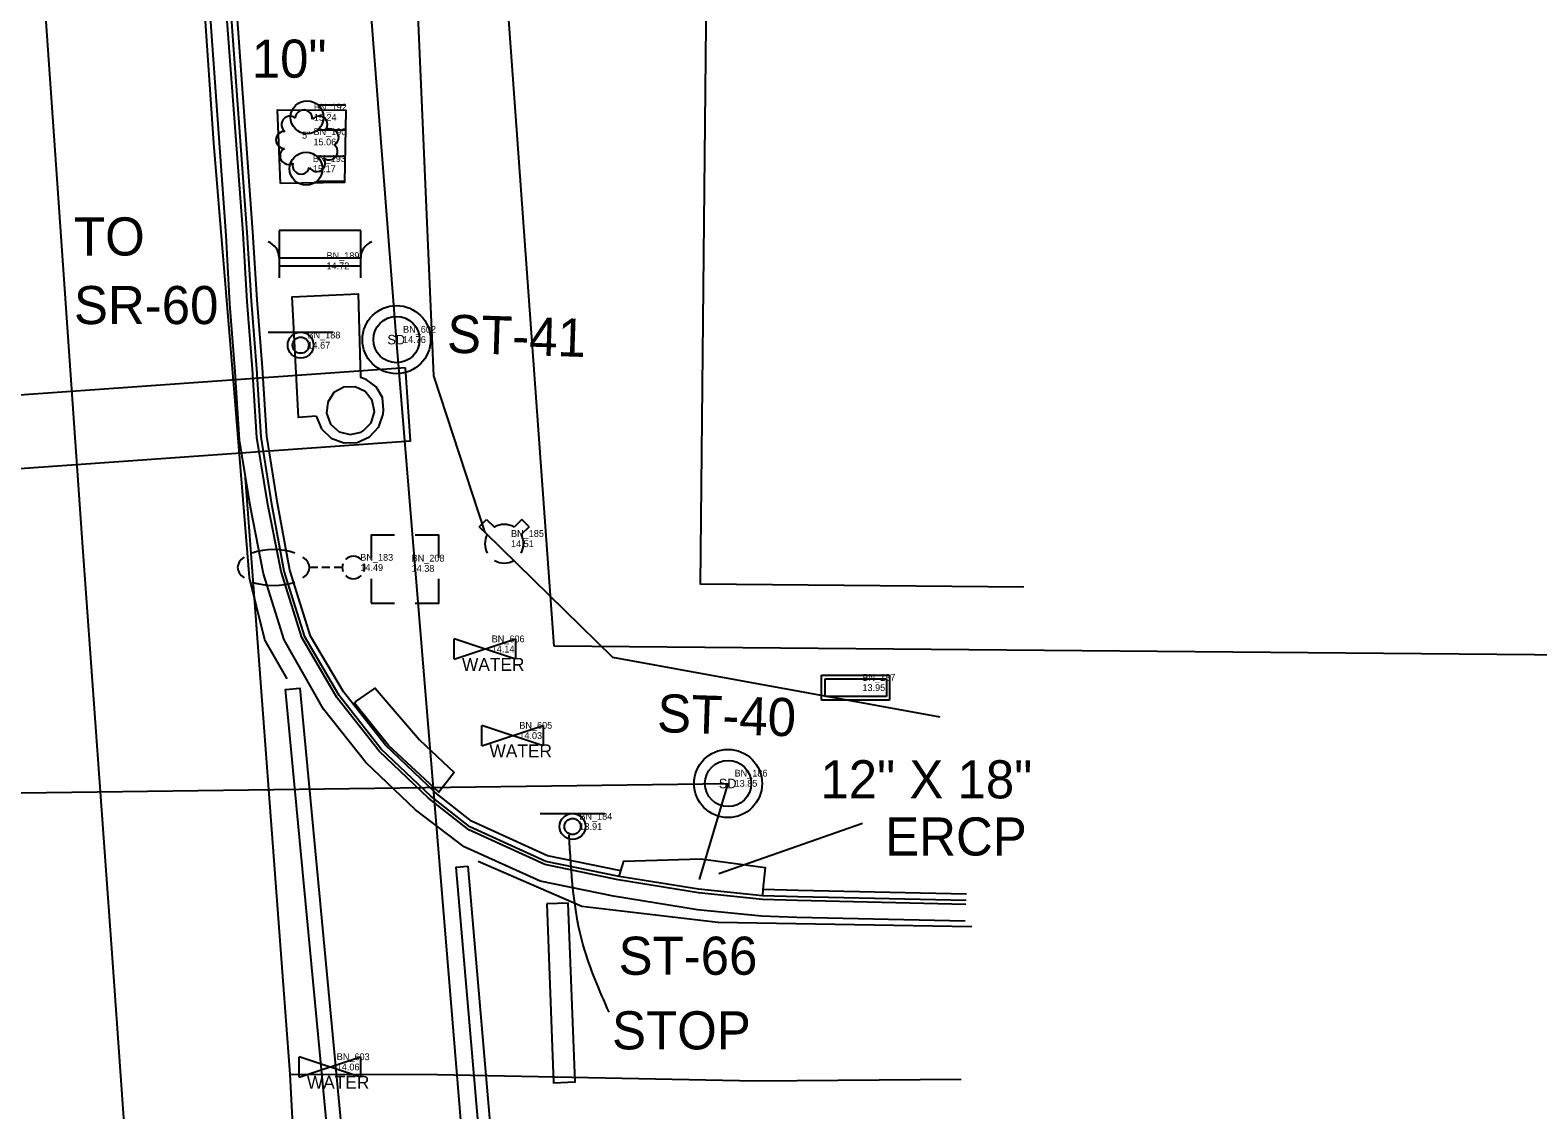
# Model space of a CAD drawing. Extents: x 509744 to 512285, y 1314862 to 1316822.
# Drawn here: x 511240.3 to 511351, y 1315303.3 to 1315382.6 of the extents above; entities that cross this region are included whole.
import ezdxf

# ---------------------------------------------------------------- set-up
doc = ezdxf.new("R2010")
doc.units = 0
for name, color, linetype in [('Bench_ep', 7, 'Continuous'), ('Building_ep', 7, 'Continuous'), ('CGBack_ep', 7, 'Continuous'), ('CGep_ep', 7, 'Continuous'), ('CGFace_ep', 7, 'Continuous'), ('CurbRampWarning_ep', 7, 'Continuous'), ('FireHydrant_ep', 7, 'Continuous'), ('FloodLight_ep', 7, 'Continuous'), ('InletCurb_ep', 7, 'Continuous'), ('JunctBox_ep', 7, 'Continuous'), ('LaneLine_ep', 7, 'Continuous'), ('Luminaire_ep', 7, 'Continuous'), ('ManholeSW_ep', 7, 'Continuous'), ('NonPlottingEle_dp', 7, 'Continuous'), ('PavtAsphalt_ep', 7, 'Continuous'), ('PavtAsphaltCrown_ep', 7, 'Continuous'), ('PavtBreak_ep', 7, 'Continuous'), ('PavtBrick_ep', 7, 'Continuous'), ('PipeCulvert_ep', 7, 'Continuous'), ('PMRK_ep', 7, 'Continuous'), ('PullBox_ep', 7, 'Continuous'), ('RWLine_ep', 7, 'Continuous'), ('SignSingle_ep', 7, 'Continuous'), ('SignTrussOH_ep', 7, 'Continuous'), ('Slopes_ep', 7, 'Continuous'), ('TextElevLabel', 7, 'Continuous'), ('TextPtLabel', 7, 'Continuous'), ('TextTopoLabel_ep', 7, 'Continuous'), ('TreeOak_ep', 7, 'Continuous'), ('ValveWater_ep', 7, 'Continuous')]:
    doc.layers.add(name, color=color, linetype=linetype)

msp = doc.modelspace()

# ---------------------------------------------------------------- linework, layer by layer
at = {"layer": 'Bench_ep'}
for p, q in [((511264.55, 1315367.9), (511258.55, 1315367.9)), ((511258.55, 1315367.9), (511258.55, 1315364.42)), ((511264.55, 1315364.42), (511264.55, 1315367.9)), ((511258.55, 1315365.9), (511264.55, 1315365.9)), ((511258.55, 1315365.3), (511264.55, 1315365.3))]:
    msp.add_line(p, q, dxfattribs=at)
for centre, start, end in [((511257.3, 1315365.89), 0.2359, 69.1544), ((511265.81, 1315365.89), 110.8456, 179.7641)]:
    msp.add_arc(centre, 1.26, start, end, dxfattribs=at)
at = {"layer": 'Building_ep'}
msp.add_lwpolyline([(511313.25, 1315341.71), (511289.5, 1315341.91), (511290.04, 1315395.14), (511275.71, 1315395.11), (511269.48, 1315477.6), (511270.95, 1315477.72), (511267.4, 1315525.27)], dxfattribs=at)
at = {"layer": 'CGBack_ep'}
for points in [[(511283.66, 1315320.87), (511278.26, 1315321.97), (511272.69, 1315324.51), (511270.02, 1315326.63), (511266.38, 1315330.09), (511263.29, 1315334.02), (511260.86, 1315338.1), (511259.34, 1315342.94), (511258.44, 1315347.86), (511257.65, 1315352.8), (511257.34, 1315357.8), (511256.95, 1315362.8), (511256.63, 1315367.8), (511254.47, 1315397.69), (511253.52, 1315411.72), (511253.19, 1315416.58), (511251.05, 1315446.49), (511250.66, 1315452.11), (511248.55, 1315482.03), (511246.42, 1315511.96), (511244.35, 1315541.88), (511243.07, 1315560.3), (511242.79, 1315565.27), (511242.88, 1315571.45)], [(511309.04, 1315319.15), (511296.67, 1315319.41), (511294.08, 1315319.49)]]:
    msp.add_lwpolyline(points, dxfattribs=at)
at = {"layer": 'CGep_ep'}
msp.add_lwpolyline([(511309, 1315318.4), (511296.64, 1315318.69), (511294.05, 1315318.77), (511289.35, 1315319.25), (511283.47, 1315320.21), (511278.08, 1315321.34), (511272.5, 1315323.88), (511269.53, 1315326.2), (511265.9, 1315329.66), (511262.8, 1315333.59), (511260.22, 1315338.01), (511258.7, 1315342.85), (511257.74, 1315347.76), (511256.92, 1315352.69), (511256.6, 1315357.7), (511256.22, 1315362.69), (511255.91, 1315367.7), (511253.66, 1315397.63)], dxfattribs=at)
at = {"layer": 'CGFace_ep'}
for points in [[(511283.54, 1315320.46), (511278.14, 1315321.56), (511272.57, 1315324.1), (511269.7, 1315326.35), (511266.06, 1315329.81), (511262.97, 1315333.74), (511260.44, 1315338.04), (511258.92, 1315342.88), (511258.03, 1315347.8), (511257.23, 1315352.74), (511256.92, 1315357.74), (511256.53, 1315362.74), (511256.21, 1315367.74), (511254.03, 1315397.66), (511253, 1315411.69), (511252.66, 1315416.54), (511250.5, 1315446.46), (511250.11, 1315452.08), (511248.04, 1315482), (511245.93, 1315511.93), (511243.85, 1315541.85), (511242.57, 1315560.27), (511242.29, 1315565.3), (511242.29, 1315571.48)], [(511309.02, 1315318.68), (511296.65, 1315318.96), (511294.06, 1315319.04)]]:
    msp.add_lwpolyline(points, dxfattribs=at)
at = {"layer": 'CurbRampWarning_ep'}
msp.add_lwpolyline([(511264.19, 1315333.31), (511265.62, 1315334.28), (511268.86, 1315330.49), (511271.41, 1315328.08), (511270.28, 1315326.65), (511266.6, 1315330.08), (511264.09, 1315333.17)], close=True, dxfattribs=at)
at = {"layer": 'FireHydrant_ep'}
for p, q in [((511273.26, 1315346.13), (511273.79, 1315346.67)), ((511273.26, 1315346.13), (511273.85, 1315345.57)), ((511273.79, 1315346.67), (511274.37, 1315346.11)), ((511276.39, 1315346.67), (511275.81, 1315346.11)), ((511276.92, 1315346.13), (511276.33, 1315345.57)), ((511276.92, 1315346.13), (511276.39, 1315346.67))]:
    msp.add_line(p, q, dxfattribs=at)
for start, end in [(59.4735, 120.5265), (151.2674, 208.7326), (331.2674, 28.7326), (239.4735, 300.5265)]:
    msp.add_arc((511275.09, 1315344.89), 1.42, start, end, dxfattribs=at)
at = {"layer": 'FloodLight_ep'}
for p, q in [((511261.4, 1315377.13), (511263.42, 1315377.13)), ((511261.4, 1315375.29), (511263.42, 1315375.29)), ((511261.33, 1315373.35), (511263.35, 1315373.35)), ((511261.33, 1315371.51), (511263.35, 1315371.51))]:
    msp.add_line(p, q, dxfattribs=at)
for centre in [(511260.61, 1315376.21), (511260.54, 1315372.43)]:
    msp.add_circle(centre, 1.21, dxfattribs=at)
at = {"layer": 'InletCurb_ep'}
for points in [[(511283.54, 1315320.46), (511283.66, 1315320.87), (511283.87, 1315321.57), (511289.52, 1315321.74), (511294.25, 1315321.1), (511294.08, 1315319.49), (511294.06, 1315319.04)], [(511294.06, 1315319.04), (511289.36, 1315319.52), (511283.54, 1315320.46)]]:
    msp.add_lwpolyline(points, dxfattribs=at)
at = {"layer": 'JunctBox_ep'}
for p, q in [((511298.4, 1315335.23), (511303.4, 1315335.23)), ((511298.4, 1315333.4), (511298.4, 1315335.23)), ((511298.66, 1315334.97), (511303.16, 1315334.97)), ((511298.66, 1315333.66), (511298.66, 1315334.97)), ((511303.16, 1315334.97), (511303.16, 1315333.66)), ((511303.4, 1315335.23), (511303.4, 1315333.4)), ((511303.4, 1315333.4), (511298.4, 1315333.4)), ((511303.16, 1315333.66), (511298.66, 1315333.66))]:
    msp.add_line(p, q, dxfattribs=at)
at = {"layer": 'LaneLine_ep'}
msp.add_lwpolyline([(511252.11, 1315233.88), (511249.8, 1315265.32), (511246.34, 1315314.13), (511244.12, 1315344.98)], dxfattribs=at)
at = {"layer": 'Luminaire_ep'}
for p, q in [((511261.39, 1315343.14), (511260.79, 1315343.14)), ((511262.29, 1315343.14), (511261.69, 1315343.14)), ((511263.19, 1315343.14), (511262.59, 1315343.14))]:
    msp.add_line(p, q, dxfattribs=at)
for start, end in [(45, 135), (159.9115, 200.0885), (339.9115, 20.0885), (225, 315)]:
    msp.add_arc((511264.02, 1315343.14), 0.825, start, end, dxfattribs=at)
for start_param, end_param in [(5.668326, 6.898045), (4.075781, 5.348997), (2.526733, 3.756452), (0.934187, 2.207405)]:
    msp.add_ellipse((511258.15, 1315343.14), major_axis=(-2.64, 0), ratio=0.5, start_param=start_param, end_param=end_param, dxfattribs=at)
at = {"layer": 'ManholeSW_ep'}
for centre, radius in [((511267.18, 1315359.88), 2.5), ((511267.18, 1315359.88), 1.7), ((511291.53, 1315327.28), 2.5), ((511291.53, 1315327.28), 1.7)]:
    msp.add_circle(centre, radius, dxfattribs=at)
at = {"layer": 'NonPlottingEle_dp'}
msp.add_line((511290.86, 1315320.68), (511301.4, 1315324.36), dxfattribs=at)
at = {"layer": 'PavtAsphalt_ep'}
msp.add_lwpolyline([(511308.95, 1315317.18), (511296.58, 1315317.44), (511293.99, 1315317.53), (511289.29, 1315318), (511283.12, 1315319.01), (511277.72, 1315320.11), (511272.14, 1315322.64), (511268.57, 1315325.35), (511264.93, 1315328.81), (511261.83, 1315332.74), (511258.94, 1315337.83), (511257.42, 1315342.67), (511256.46, 1315347.58), (511255.64, 1315352.52), (511255.32, 1315357.52), (511254.94, 1315362.51), (511254.68, 1315367.53), (511252.51, 1315397.54)], dxfattribs=at)
at = {"layer": 'PavtAsphaltCrown_ep'}
msp.add_lwpolyline([(511264.74, 1315353.18), (511265.32, 1315353.78), (511265.56, 1315354.58), (511265.4, 1315355.4), (511264.89, 1315356.06), (511264.14, 1315356.42), (511263.31, 1315356.4), (511262.58, 1315355.99), (511262.13, 1315355.3), (511262.04, 1315354.47), (511262.34, 1315353.68), (511262.96, 1315353.12), (511263.77, 1315352.91), (511264.58, 1315353.09)], close=True, dxfattribs=at)
msp.add_lwpolyline([(511259.35, 1315305.92), (511270.2, 1315305.91), (511293.6, 1315305.43), (511308.66, 1315305.57)], dxfattribs=at)
at = {"layer": 'PavtBreak_ep'}
msp.add_lwpolyline([(511256.05, 1315350.05), (511259.35, 1315305.92), (511261.42, 1315266.3)], dxfattribs=at)
at = {"layer": 'PavtBrick_ep'}
msp.add_lwpolyline([(511258.67, 1315371.35), (511258.44, 1315376.75), (511263.47, 1315376.74), (511263.37, 1315371.42)], close=True, dxfattribs=at)
for points in [[(511261.27, 1315354.26), (511259.99, 1315354.16), (511259.52, 1315363.02), (511264.36, 1315363.25), (511264.53, 1315357.09)], [(511266.23, 1315354.72), (511266.14, 1315355.62), (511265.68, 1315356.41), (511264.95, 1315356.95), (511264.53, 1315357.09)], [(511261.27, 1315354.26), (511261.66, 1315353.34), (511262.37, 1315352.65), (511263.3, 1315352.29), (511264.3, 1315352.32), (511265.2, 1315352.73), (511265.88, 1315353.47), (511266.21, 1315354.4), (511266.23, 1315354.72)]]:
    msp.add_lwpolyline(points, dxfattribs=at)
at = {"layer": 'PipeCulvert_ep'}
for p, q in [((511258.61, 1315469.47), (511267.16, 1315359.89)), ((511267.16, 1315359.89), (511284.6, 1315148.05)), ((511204.45, 1315326.14), (511291.53, 1315327.28)), ((511289.44, 1315320.24), (511291.53, 1315327.28))]:
    msp.add_line(p, q, dxfattribs=at)
at = {"layer": 'PMRK_ep'}
for points in [[(511240.68, 1315559.35), (511242.53, 1315534.42), (511243.24, 1315524.81), (511244.8, 1315499.86), (511245.01, 1315496.46), (511246.86, 1315471.53), (511248.71, 1315446.6), (511249.61, 1315434.57), (511251.32, 1315409.63), (511253.04, 1315384.69), (511253.75, 1315374.31), (511255.25, 1315355.97), (511256.35, 1315342.41), (511257.31, 1315338.55), (511257.5, 1315337.78), (511259.12, 1315334.96)], [(511244.12, 1315344.98), (511242.38, 1315369.92), (511240.64, 1315394.86), (511238.9, 1315419.8), (511237.16, 1315444.74), (511235.41, 1315469.68), (511233.98, 1315490.19)], [(511273.19, 1315321.58), (511280.79, 1315318.28), (511290.78, 1315317.09), (511309.43, 1315316.77)]]:
    msp.add_lwpolyline(points, dxfattribs=at)
for points in [[(511264.29, 1315278.64), (511259.02, 1315334.18), (511260.07, 1315334.28), (511265.33, 1315278.73)], [(511272.42, 1315321.21), (511275.06, 1315290.47), (511274.21, 1315290.4), (511271.56, 1315321.13)], [(511278.21, 1315318.44), (511278.72, 1315305.3), (511280.3, 1315305.36), (511279.79, 1315318.5)]]:
    msp.add_lwpolyline(points, close=True, dxfattribs=at)
at = {"layer": 'PullBox_ep'}
for points in [[(511267.04, 1315345.53), (511265.31, 1315345.53), (511265.31, 1315343.86)], [(511270.3, 1315343.86), (511270.3, 1315345.53), (511268.54, 1315345.53)], [(511265.31, 1315342.31), (511265.31, 1315340.53)], [(511268.54, 1315340.53), (511270.3, 1315340.53), (511270.3, 1315342.31)], [(511265.31, 1315340.53), (511267.04, 1315340.53)]]:
    msp.add_lwpolyline(points, dxfattribs=at)
at = {"layer": 'RWLine_ep'}
for p, q in [((511278.76, 1315337.37), (511261.23, 1315580.31)), ((511589.77, 1315334.64), (511278.76, 1315337.37))]:
    msp.add_line(p, q, dxfattribs=at)
at = {"layer": 'SignSingle_ep'}
for p, q in [((511257.76, 1315360.42), (511262.51, 1315360.42)), ((511277.74, 1315325.07), (511282.49, 1315325.07))]:
    msp.add_line(p, q, dxfattribs=at)
for centre, radius in [((511260.14, 1315359.47), 0.95), ((511260.14, 1315359.47), 0.594), ((511280.11, 1315324.12), 0.95), ((511280.11, 1315324.12), 0.594)]:
    msp.add_circle(centre, radius, dxfattribs=at)
at = {"layer": 'SignTrussOH_ep'}
msp.add_lwpolyline([(511267.84, 1315357.81), (511124.68, 1315347.68), (511125.06, 1315342.32), (511268.22, 1315352.45)], close=True, dxfattribs=at)
at = {"layer": 'Slopes_ep'}
msp.add_lwpolyline([(511307.12, 1315332.14), (511283.06, 1315336.54), (511273.7, 1315345.72), (511269.92, 1315357.22), (511268.63, 1315387.08), (511265.4, 1315432.53), (511263.39, 1315478.03), (511259.99, 1315512.19), (511255.38, 1315552.32), (511254.62, 1315569.99), (511253.19, 1315580.1), (511262.52, 1315585.27), (511268.86, 1315587.2), (511280.73, 1315589.96), (511302.82, 1315589.29)], dxfattribs=at)
at = {"layer": 'TextTopoLabel_ep'}
msp.add_spline([(511279.84, 1315323.52), (511280.89, 1315315.33), (511282.77, 1315310.49)], degree=3, dxfattribs=at)
at = {"layer": 'TreeOak_ep'}
for centre, radius, start, end in [((511259.35, 1315375.67), 0.624, 50.7185, 233.084), ((511260.37, 1315376.12), 0.629, 355.3943, 176.6549), ((511261.49, 1315375.67), 0.627, 315.0898, 140.6833), ((511258.95, 1315374.55), 0.625, 87.3095, 269.5618), ((511262.31, 1315374.73), 0.626, 299.4354, 127.2613), ((511259.25, 1315373.38), 0.626, 119.4469, 301.0197), ((511262.23, 1315373.7), 0.623, 229.2872, 51.2025), ((511260.17, 1315372.67), 0.625, 164.2871, 346.2767), ((511261.32, 1315372.85), 0.628, 211.1877, 36.8199)]:
    msp.add_arc(centre, radius, start, end, dxfattribs=at)
at = {"layer": 'ValveWater_ep'}
for p, q in [((511275.92, 1315336.4), (511271.42, 1315337.9)), ((511271.42, 1315336.4), (511275.92, 1315337.9)), ((511271.42, 1315336.4), (511271.42, 1315337.9)), ((511275.92, 1315337.9), (511275.92, 1315336.4)), ((511277.95, 1315330.05), (511273.45, 1315331.55)), ((511273.45, 1315330.05), (511277.95, 1315331.55)), ((511273.45, 1315330.05), (511273.45, 1315331.55)), ((511277.95, 1315331.55), (511277.95, 1315330.05)), ((511264.54, 1315305.71), (511260.04, 1315307.21)), ((511260.04, 1315305.71), (511264.54, 1315307.21)), ((511260.04, 1315305.71), (511260.04, 1315307.21)), ((511264.54, 1315307.21), (511264.54, 1315305.71))]:
    msp.add_line(p, q, dxfattribs=at)

# ---------------------------------------------------------------- texts
at = {"layer": 'ManholeSW_ep'}
for p in [(511266.51, 1315359.53), (511290.85, 1315326.93)]:
    msp.add_text('SD', height=0.7, dxfattribs=at).set_placement(p)
at = {"layer": 'NonPlottingEle_dp'}
for s, rotation, p in [('ST-41', 358.1578, (511270.86, 1315358.93)), ('ST-40', 358.1578, (511286.29, 1315331.06)), ('12" X 18"', 359.9807, (511298.31, 1315326.19)), ('ERCP', 359.9807, (511303.07, 1315321.99))]:
    msp.add_text(s, height=2.8, rotation=rotation, dxfattribs=at).set_placement(p)
msp.add_text('ST-66', height=2.8, dxfattribs=at).set_placement((511283.49, 1315313.23))
at = {"layer": 'TextElevLabel'}
for s, p in [('15.24', (511261.11, 1315375.96)), ('15.06', (511261.08, 1315374.15)), ('15.17', (511261.04, 1315372.18)), ('14.72', (511262.04, 1315365.05)), ('14.67', (511260.64, 1315359.22)), ('14.76', (511267.66, 1315359.64)), ('14.51', (511275.59, 1315344.64)), ('14.49', (511264.52, 1315342.89)), ('14.38', (511268.29, 1315342.83)), ('14.14', (511274.17, 1315336.9)), ('13.95', (511301.4, 1315334.07)), ('14.03', (511276.2, 1315330.55)), ('13.85', (511292.01, 1315327.04)), ('13.91', (511280.61, 1315323.87)), ('14.06', (511262.79, 1315306.21))]:
    msp.add_text(s, height=0.5, dxfattribs=at).set_placement(p)
at = {"layer": 'TextPtLabel'}
for s, p in [('BN_192', (511261.11, 1315376.71)), ('BN_190', (511261.08, 1315374.9)), ('BN_193', (511261.04, 1315372.93)), ('BN_189', (511262.04, 1315365.8)), ('BN_188', (511260.64, 1315359.97)), ('BN_602', (511267.66, 1315360.39)), ('BN_185', (511275.59, 1315345.39)), ('BN_183', (511264.52, 1315343.64)), ('BN_208', (511268.29, 1315343.58)), ('BN_606', (511274.17, 1315337.65)), ('BN_187', (511301.4, 1315334.82)), ('BN_605', (511276.2, 1315331.3)), ('BN_186', (511292.01, 1315327.79)), ('BN_184', (511280.61, 1315324.62)), ('BN_603', (511262.79, 1315306.96))]:
    msp.add_text(s, height=0.5, dxfattribs=at).set_placement(p)
at = {"layer": 'TextTopoLabel_ep'}
for s, height, p in [('10"', 2.8, (511256.55, 1315379.12)), ('5"', 0.5, (511260.24, 1315374.65)), ('TO ', 2.8, (511243.49, 1315366.06)), ('SR-60', 2.8, (511243.49, 1315361.02)), ('STOP', 2.8, (511283.01, 1315307.75))]:
    msp.add_text(s, height=height, dxfattribs=at).set_placement(p)
at = {"layer": 'ValveWater_ep'}
for p in [(511271.99, 1315335.55), (511274.01, 1315329.2), (511260.6, 1315304.86)]:
    msp.add_text('WATER', height=0.95, dxfattribs=at).set_placement(p)

doc.saveas('drawing.dxf')
